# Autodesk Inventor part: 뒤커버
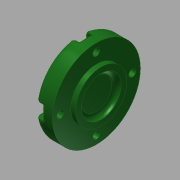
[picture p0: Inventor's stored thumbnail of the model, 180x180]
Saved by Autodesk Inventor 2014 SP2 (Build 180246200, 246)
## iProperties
Created: 2015-11
Part Number: 뒤커버
Material: 알루미늄 6061
Document SubType Name: Modeling
Designer: mduedu
Density: 1 g/cm^3
Appearance: 매끄러움 - 짙은 산림 녹색
Author: mduedu
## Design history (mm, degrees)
sketch "스케치1"
  geometry: L1 (-7, 0)-(7, 0); L2 (-7, 0)-(-7, 27.5); L3 (-7, 27.5)-(4, 27.5); L4 (4, 27.5)-(4, 16); L5 (4, 16)-(7, 16); L6 (7, 16)-(7, 0); 2 further points
  constraints: 12 end point, 3 perpendicular, 2 parallel, 1 coincident, 1 horizontal, 1 midpoint
  dimensions: "d0" = 14 distance of L1.start L1.end; "d1" = 55 diameter of L3 L1; "d2" = 3 distance of L4.end L5.end; "d3" = 32 diameter of L5 L1
revolve "회전1" sketch "스케치1" stored, may be unused: angle "d4" = 90 deg
hole "구멍1" diameter "d7" = 25; stored, may be unused: countersink angle "d11" = 90 deg, drill point angle "d13" = 0 deg; dims "d5" = 10, "d6" = 10, "d8" = 6, "d9" = 4, "d10" = 2, "d12" = 3
fillet "모깎기2" dims "d36" = 3
fillet "모깎기3" dims "d37" = 3
sketch "스케치2" dims "d39" = 45
  geometry: C1 r 12.846 at (0, 0) reference; C2 r 24.5 at (0, 0) reference; 6 further points
  constraints: 2 vertical alignment, 1 coincident, 7 other
  dimensions: "d42" = 360 deg dimension on point (0, 0) point (0, 22.5) (derived)
sketch "스케치3"
  geometry: 8 further points
  constraints: 4 coincident
hole "구멍4" sketch "스케치3" at (-22.5, 0), (0, -22.5), (22.5, 0), (0, 22.5) diameter "d44" = 4.5; stored, may be unused: countersink angle "d48" = 90 deg, drill point angle "d50" = 0 deg; dims "d45" = 6, "d46" = 8, "d47" = 4.6, "d49" = 8
sketch "스케치4"
  geometry: L1 (-4, 0)-(-4, -4.708); L2 (4, 0)-(4, -4.708); A1 r 4 centre (0, 0) between (-4, 0) and (4, 0) reference; A2 r 27.5 centre (0, 22.5) between (-4, -4.708) and (4, -4.708) reference; 3 further points
  constraints: 4 end point, 4 point on circle, 2 tangent, 1 parallel, 1 vertical
extrude "돌출1" cut sketch "스케치4" stored distance "d51" = 0; taper "d52" = 0 deg
fillet "모깎기5" dims "d56" = 0.3
fillet "모깎기6" dims "d57" = 1
node "솔리드1"
pattern_circular "원형 패턴1" dims angle "d54" = 360 deg
